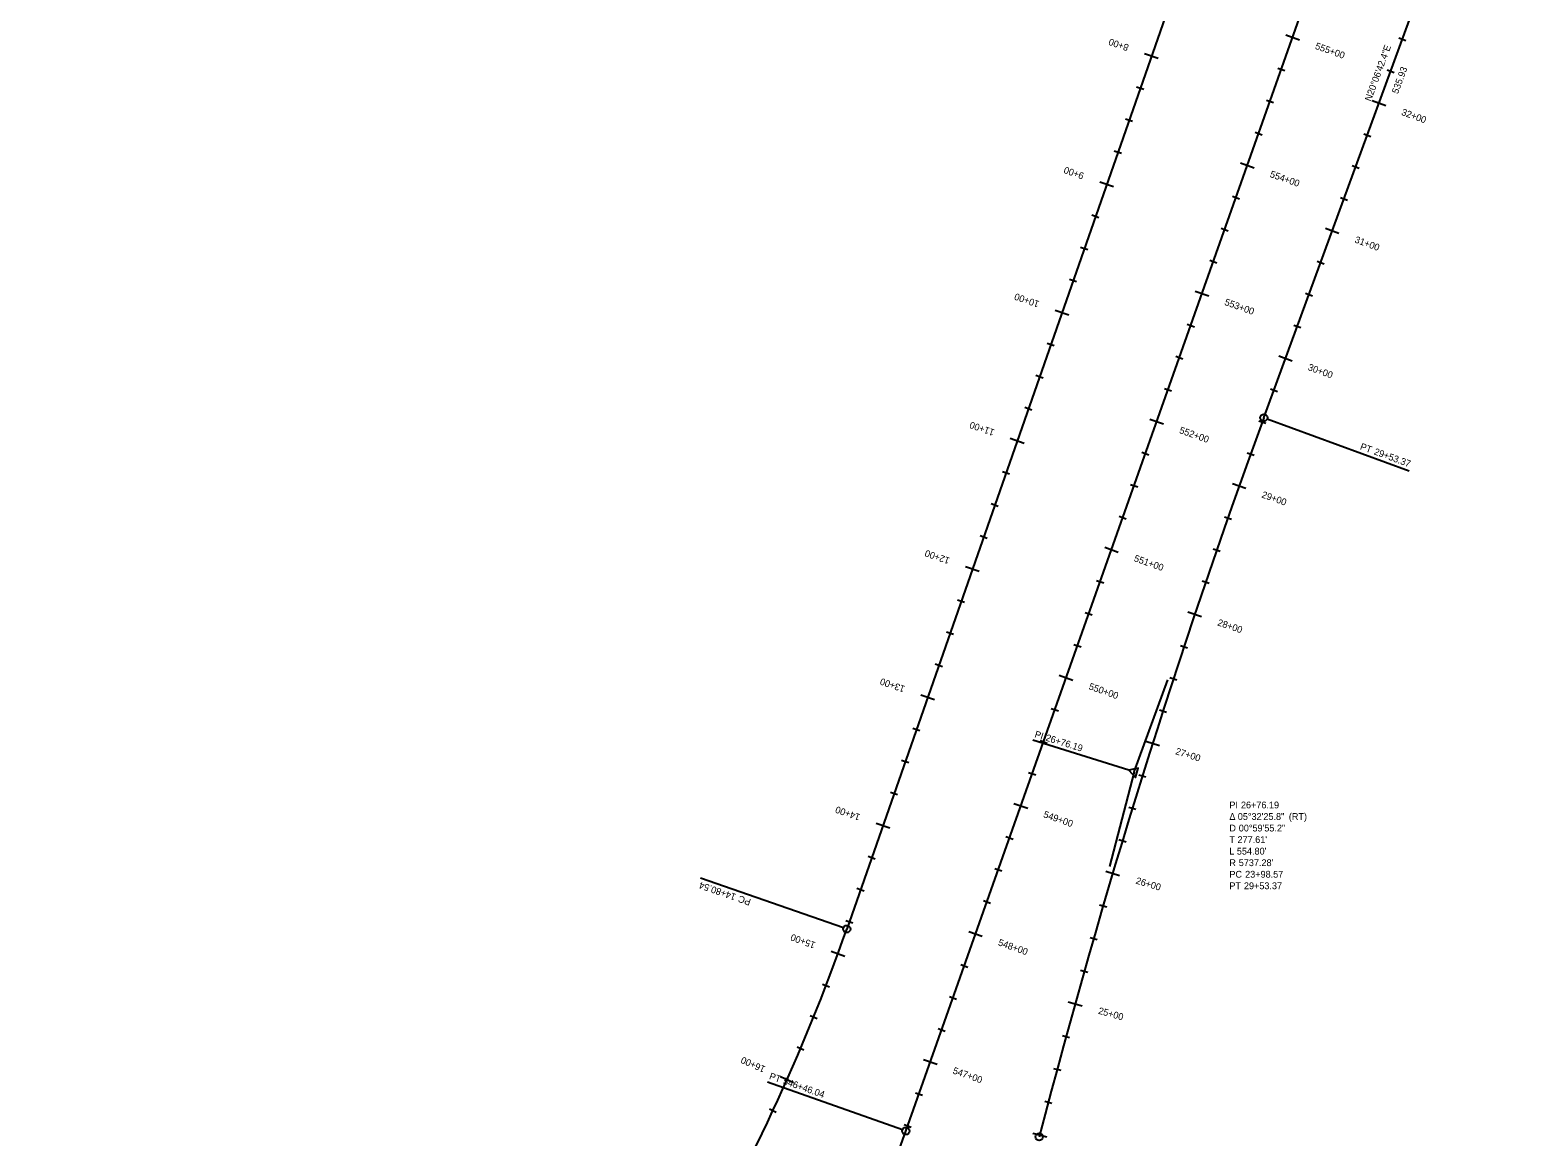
# Model space of a CAD drawing. Extents: x 2300830 to 2307917, y 756066 to 766359.
# Drawn here: x 2303797 to 2304907, y 763421 to 764235 of the extents above; entities that cross this region are included whole.
import ezdxf

# ---------------------------------------------------------------- set-up
doc = ezdxf.new("R2010")
doc.units = 0
for name, color, linetype in [('Default', 7, 'Continuous'), ('Draft_Bearing Label', 7, 'Continuous'), ('Draft_Curve Data Label', 7, 'Continuous'), ('Draft_Station Cardinal Lines', 7, 'Continuous'), ('Draft_Station Cardinal Points', 7, 'Continuous'), ('Draft_Station Labels Major', 7, 'Continuous'), ('Draft_Station Ticks Major', 7, 'Continuous'), ('Draft_Station Ticks Minor', 7, 'Continuous'), ('Geom_Baseline', 7, 'Continuous')]:
    doc.layers.add(name, color=color, linetype=linetype)

msp = doc.modelspace()

# ---------------------------------------------------------------- linework, layer by layer
at = {"layer": 'Default'}
for p, q in [((2304441.8, 763425), (2305466.9, 766322.6)), ((2304886.2, 764971.5), (2304398.3, 763573.7)), ((2304705.3, 763950.1), (2304889.6, 764453.3))]:
    msp.add_line(p, q, dxfattribs=at)
for centre, radius, start, end in [((2310092.8, 761977.3), 5737.3, 159.88822, 165.42872), ((2303045.6, 764045.7), 1432.7, 317.6167, 340.7615), ((2294501, 766942), 10544.6, 331.8357, 340.5164)]:
    msp.add_arc(centre, radius, start, end, dxfattribs=at)
at = {"layer": 'Draft_Station Cardinal Lines'}
for p, q in [((2304707.8, 763949.2), (2304812.4, 763910.9)), ((2304609.9, 763689.4), (2304634.6, 763757)), ((2304605.9, 763690.6), (2304535.4, 763712.6)), ((2304609.9, 763689.4), (2304591.8, 763619.7)), ((2304395.8, 763574.5), (2304290.7, 763611.2)), ((2304439.3, 763425.9), (2304340, 763461))]:
    msp.add_line(p, q, dxfattribs=at)
msp.add_lwpolyline([(2304605.9, 763690.6), (2304610.8, 763685.3), (2304612.9, 763692.2)], close=True, dxfattribs=at)
at = {"layer": 'Draft_Station Cardinal Points'}
for p, q in [((2304705.3, 763950.1), (2304705.3, 763950.1)), ((2304812.4, 763910.9), (2304812.4, 763910.9)), ((2304535.4, 763712.6), (2304535.4, 763712.6)), ((2304609.9, 763689.4), (2304609.9, 763689.4)), ((2304290.7, 763611.2), (2304290.7, 763611.2)), ((2304398.3, 763573.7), (2304398.3, 763573.7)), ((2304340, 763461), (2304340, 763461)), ((2304441.8, 763425), (2304441.8, 763425)), ((2304540, 763420.7), (2304540, 763420.7))]:
    msp.add_line(p, q, dxfattribs=at)
for centre in [(2304705.3, 763950.1), (2304398.3, 763573.7), (2304441.8, 763425), (2304540, 763420.7)]:
    msp.add_circle(centre, 2.67, dxfattribs=at)
at = {"layer": 'Draft_Station Ticks Major'}
for p, q in [((2304721.6, 764231.9), (2304731.6, 764228.3)), ((2304627.6, 764214.4), (2304617.6, 764217.9)), ((2304785.1, 764183.5), (2304795.1, 764179.8)), ((2304688.2, 764137.6), (2304698.2, 764134)), ((2304594.7, 764120), (2304584.6, 764123.5)), ((2304750.7, 764089.6), (2304760.7, 764085.9)), ((2304654.9, 764043.3), (2304664.9, 764039.8)), ((2304561.7, 764025.6), (2304551.7, 764029.1)), ((2304716.4, 763995.7), (2304726.3, 763992)), ((2304621.5, 763949), (2304631.5, 763945.5)), ((2304528.8, 763931.2), (2304518.7, 763934.7)), ((2304682.2, 763901.7), (2304692.2, 763898.1)), ((2304588.2, 763854.8), (2304598.2, 763851.2)), ((2304495.8, 763836.8), (2304485.8, 763840.3)), ((2304649.5, 763807.1), (2304659.5, 763803.7)), ((2304554.8, 763760.5), (2304564.8, 763756.9)), ((2304462.9, 763742.4), (2304452.8, 763745.9)), ((2304618.4, 763711.9), (2304628.5, 763708.7)), ((2304521.4, 763666.2), (2304531.5, 763662.7)), ((2304429.9, 763647.9), (2304419.9, 763651.4)), ((2304589, 763616.2), (2304599.2, 763613.2)), ((2304488.1, 763571.9), (2304498.1, 763568.4)), ((2304396.8, 763553.5), (2304386.8, 763557.1)), ((2304561.3, 763520.1), (2304571.5, 763517.2)), ((2304454.7, 763477.7), (2304464.8, 763474.1)), ((2304359.2, 763460.5), (2304349.5, 763464.8)), ((2304535.2, 763423.4), (2304545.5, 763420.8))]:
    msp.add_line(p, q, dxfattribs=at)
at = {"layer": 'Draft_Station Ticks Minor'}
for p, q in [((2304804.7, 764229.6), (2304809.9, 764227.7)), ((2304715.7, 764207.4), (2304720.9, 764205.6)), ((2304796.1, 764206.1), (2304801.3, 764204.2)), ((2304616.9, 764191.7), (2304611.7, 764193.5)), ((2304707.3, 764183.9), (2304712.5, 764182)), ((2304608.7, 764168.1), (2304603.5, 764169.9)), ((2304699, 764160.3), (2304704.2, 764158.4)), ((2304778.9, 764159.1), (2304784.1, 764157.2)), ((2304600.5, 764144.5), (2304595.2, 764146.3)), ((2304770.4, 764135.7), (2304775.5, 764133.8)), ((2304682.3, 764113.1), (2304687.5, 764111.3)), ((2304761.8, 764112.2), (2304766.9, 764110.3)), ((2304584, 764097.3), (2304578.8, 764099.1)), ((2304674, 764089.6), (2304679.2, 764087.7)), ((2304575.7, 764073.7), (2304570.5, 764075.5)), ((2304665.6, 764066), (2304670.8, 764064.2)), ((2304744.6, 764065.2), (2304749.7, 764063.3)), ((2304567.5, 764050.1), (2304562.3, 764051.9)), ((2304736, 764041.8), (2304741.1, 764039.9)), ((2304649, 764018.9), (2304654.2, 764017)), ((2304727.4, 764018.3), (2304732.6, 764016.4)), ((2304551, 764002.9), (2304545.8, 764004.7)), ((2304640.6, 763995.3), (2304645.8, 763993.5)), ((2304542.8, 763979.3), (2304537.6, 763981.1)), ((2304632.3, 763971.7), (2304637.5, 763969.9)), ((2304710.2, 763971.3), (2304715.4, 763969.4)), ((2304534.6, 763955.6), (2304529.3, 763957.5)), ((2304701.6, 763947.9), (2304706.8, 763946)), ((2304615.6, 763924.6), (2304620.8, 763922.8)), ((2304693, 763924.3), (2304698.2, 763922.5)), ((2304518.1, 763908.4), (2304512.9, 763910.3)), ((2304607.3, 763901), (2304612.5, 763899.2)), ((2304509.8, 763884.8), (2304504.6, 763886.7)), ((2304598.9, 763877.5), (2304604.1, 763875.6)), ((2304676.3, 763877.2), (2304681.5, 763875.4)), ((2304501.6, 763861.2), (2304496.4, 763863.1)), ((2304668.1, 763853.6), (2304673.3, 763851.8)), ((2304582.2, 763830.3), (2304587.5, 763828.5)), ((2304659.9, 763829.9), (2304665.2, 763828.2)), ((2304485.1, 763814), (2304479.9, 763815.8)), ((2304573.9, 763806.8), (2304579.1, 763804.9)), ((2304476.9, 763790.4), (2304471.7, 763792.2)), ((2304565.6, 763783.2), (2304570.8, 763781.3)), ((2304644, 763782.5), (2304649.2, 763780.8)), ((2304468.7, 763766.8), (2304463.4, 763768.6)), ((2304636.2, 763758.8), (2304641.4, 763757)), ((2304548.9, 763736.1), (2304554.1, 763734.2)), ((2304628.5, 763735), (2304633.7, 763733.3)), ((2304452.2, 763719.6), (2304447, 763721.4)), ((2304540.6, 763712.5), (2304545.8, 763710.6)), ((2304443.9, 763696), (2304438.7, 763697.8)), ((2304532.2, 763688.9), (2304537.4, 763687.1)), ((2304613.4, 763687.3), (2304618.6, 763685.6)), ((2304435.7, 763672.4), (2304430.5, 763674.2)), ((2304606, 763663.4), (2304611.2, 763661.8)), ((2304515.5, 763641.8), (2304520.7, 763639.9)), ((2304598.7, 763639.5), (2304603.9, 763637.9)), ((2304419.2, 763625.2), (2304414, 763627)), ((2304507.2, 763618.2), (2304512.4, 763616.4)), ((2304411, 763601.6), (2304405.8, 763603.4)), ((2304498.9, 763594.6), (2304504.1, 763592.8)), ((2304584.4, 763591.5), (2304589.7, 763590)), ((2304402.8, 763578), (2304397.5, 763579.8)), ((2304577.4, 763567.5), (2304582.7, 763566)), ((2304482.2, 763547.5), (2304487.4, 763545.7)), ((2304570.5, 763543.5), (2304575.8, 763541.9)), ((2304385.6, 763530.9), (2304380.4, 763532.9)), ((2304473.9, 763523.9), (2304479.1, 763522.1)), ((2304376.4, 763507.6), (2304371.3, 763509.7)), ((2304465.5, 763500.4), (2304470.7, 763498.5)), ((2304366.8, 763484.5), (2304361.7, 763486.6)), ((2304557.1, 763495.3), (2304562.4, 763493.8)), ((2304550.5, 763471.1), (2304555.9, 763469.7)), ((2304448.8, 763453.2), (2304454, 763451.4)), ((2304346.4, 763438.7), (2304341.4, 763441.1)), ((2304544.1, 763447), (2304549.4, 763445.6)), ((2304440.5, 763429.7), (2304445.7, 763427.8))]:
    msp.add_line(p, q, dxfattribs=at)
at = {"layer": 'Geom_Baseline'}
for p, q in [((2304441.8, 763425), (2305466.9, 766322.6)), ((2304886.2, 764971.5), (2304398.3, 763573.7)), ((2304705.3, 763950.1), (2304889.6, 764453.3))]:
    msp.add_line(p, q, dxfattribs=at)
for centre, radius, start, end in [((2310092.8, 761977.3), 5737.3, 159.88822, 165.42872), ((2303045.6, 764045.7), 1432.7, 317.6167, 340.7615), ((2294501, 766942), 10544.6, 331.8357, 340.5164)]:
    msp.add_arc(centre, radius, start, end, dxfattribs=at)

# ---------------------------------------------------------------- texts
at = {"layer": 'Draft_Bearing Label'}
for s, p in [('N20°06\'42.4"E', (2304784.2, 764182.6)), ('535.93', (2304804.1, 764188.1))]:
    msp.add_text(s, height=5, rotation=69.8882, dxfattribs=at).set_placement(p)
at = {"layer": 'Draft_Curve Data Label'}
for s, p in [('PI ', (2304680, 763662.5)), ('26+76.19', (2304688.5, 763662.5)), ('Δ ', (2304680, 763654)), ('05°32\'25.8"', (2304686.2, 763654)), (' (RT)', (2304721.9, 763654)), ('T ', (2304680, 763637)), ('D ', (2304680, 763645.5)), ("277.61'", (2304686, 763637)), ('00°59\'55.2"', (2304686.9, 763645.5)), ('L ', (2304680, 763628.5)), ("554.80'", (2304685.5, 763628.5)), ('R ', (2304680, 763620)), ("5737.28'", (2304686.9, 763620)), ('PC ', (2304680, 763611.5)), ('PT ', (2304680, 763603)), ('29+53.37', (2304690.7, 763603)), ('23+98.57', (2304691.6, 763611.5))]:
    msp.add_text(s, height=5, dxfattribs=at).set_placement(p)
at = {"layer": 'Draft_Station Cardinal Points'}
for s, rotation, p in [('PT', 339.8882, (2304775.8, 763926.9)), ('29+53.37', 339.8882, (2304786, 763923.2)), ('PI ', 342.6585, (2304536.2, 763715)), ('26+76.19', 342.6585, (2304544.3, 763712.5)), ('14+80.54', 160.7615, (2304317.2, 763599.3)), ('PC', 160.7615, (2304328.2, 763595.5)), ('PT', 340.5164, (2304340.8, 763463.4)), ('546+46.04', 340.5164, (2304351, 763459.8))]:
    msp.add_text(s, height=5, rotation=rotation, dxfattribs=at).set_placement(p)
at = {"layer": 'Draft_Station Labels Major'}
for s, rotation, p in [('8+00', 160.7615, (2304606.4, 764224.5)), ('555+00', 340.5164, (2304742.7, 764221.7)), ('32+00', 339.8882, (2304806.2, 764173.1)), ('9+00', 160.7615, (2304573.4, 764130.1)), ('554+00', 340.5164, (2304709.4, 764127.4)), ('31+00', 339.8882, (2304771.8, 764079.2)), ('10+00', 160.7615, (2304540.5, 764035.7)), ('553+00', 340.5164, (2304676, 764033.2)), ('30+00', 339.8882, (2304737.4, 763985.3)), ('11+00', 160.7615, (2304507.5, 763941.2)), ('552+00', 340.5164, (2304642.7, 763938.9)), ('29+00', 340.4212, (2304703.3, 763891.5)), ('12+00', 160.7615, (2304474.6, 763846.8)), ('551+00', 340.5164, (2304609.3, 763844.6)), ('28+00', 341.4199, (2304670.8, 763797.3)), ('13+00', 160.7615, (2304441.6, 763752.4)), ('550+00', 340.5164, (2304576, 763750.3)), ('27+00', 342.4185, (2304639.9, 763702.5)), ('14+00', 160.7615, (2304408.7, 763658)), ('549+00', 340.5164, (2304542.6, 763656.1)), ('26+00', 343.4172, (2304610.7, 763607.2)), ('15+00', 159.9834, (2304375.7, 763563.8)), ('548+00', 340.5164, (2304509.3, 763561.8)), ('25+00', 344.4158, (2304583.1, 763511.4)), ('16+00', 155.9842, (2304338.9, 763472.3)), ('547+00', 340.5164, (2304475.9, 763467.5))]:
    msp.add_text(s, height=5, rotation=rotation, dxfattribs=at).set_placement(p)

doc.saveas('drawing.dxf')
